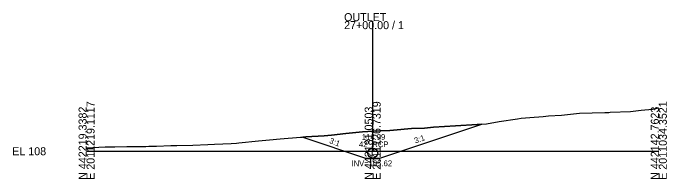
# Model space of a CAD drawing. Extents: x -26 to 1203, y -15 to 9526.
# Drawn here: x 974.3 to 1202.8, y 6990.3 to 7048.4 of the extents above; entities that cross this region are included whole.
import ezdxf

# ---------------------------------------------------------------- set-up
doc = ezdxf.new("R2010")
doc.units = 0
for name, color, linetype in [('Exist Cross Section Cell', 7, 'Continuous'), ('Exist XS Center Line Elevation Label', 7, 'Continuous'), ('Exist XS Ground Line', 7, 'Continuous'), ('Prop XS DDE', 7, 'Continuous'), ('Prop XS DDE Earthwork Shape', 7, 'Continuous'), ('Prop XS DDE Slope Text', 7, 'Continuous'), ('Prop XSC Text', 7, 'Continuous')]:
    doc.layers.add(name, color=color, linetype=linetype)

msp = doc.modelspace()

# ---------------------------------------------------------------- linework, layer by layer
at = {"layer": 'Exist Cross Section Cell'}
for p, q in [((1100, 7000), (1100, 7045.53)), ((1000, 7000), (1100, 7000)), ((1100, 7000), (1200, 7000))]:
    msp.add_line(p, q, dxfattribs=at)
at = {"layer": 'Exist XS Ground Line'}
msp.add_lwpolyline([(1000, 7001.15), (1006.47, 7001.49), (1009.86, 7001.55), (1014.12, 7001.69), (1020.69, 7001.72), (1021.77, 7001.74), (1024.39, 7001.82), (1029.43, 7002), (1031.51, 7001.99), (1037.08, 7002.16), (1042.34, 7002.33), (1044.73, 7002.48), (1050.51, 7002.74), (1052.38, 7002.85), (1053.16, 7002.92), (1060.04, 7003.66), (1063.99, 7004.05), (1067.69, 7004.31), (1074.81, 7004.88), (1075.34, 7004.91), (1076.63, 7004.99), (1083, 7005.37), (1085.64, 7005.63), (1090.65, 7006.27), (1096.46, 7006.74), (1098.3, 7006.91), (1100, 7006.99), (1102.74, 7007.12), (1105.96, 7007.26), (1107.29, 7007.38), (1113.61, 7007.91), (1118.11, 7008.12), (1121.26, 7008.38), (1128.94, 7008.91), (1136.57, 7009.37), (1139.76, 7009.63), (1144.22, 7010.41), (1150.59, 7011.34), (1151.87, 7011.57), (1154.98, 7011.78), (1159.53, 7012.19), (1161.41, 7012.43), (1165.96, 7012.6), (1172.24, 7013.28), (1181.1, 7013.51), (1182.49, 7013.6), (1183.06, 7013.65), (1190.14, 7013.88), (1193.89, 7014.4), (1197.79, 7014.73), (1200, 7015.18)], dxfattribs=at)
at = {"layer": 'Prop XS DDE'}
for p, q in [((1102.5, 6997.62), (1138.13, 7009.5)), ((1075.58, 7004.93), (1097.5, 6997.62)), ((1097.5, 6997.62), (1102.5, 6997.62))]:
    msp.add_line(p, q, dxfattribs=at)
at = {"layer": 'Prop XS DDE Earthwork Shape'}
msp.add_lwpolyline([(1102.5, 6997.62), (1138.13, 7009.5), (1136.57, 7009.37), (1128.94, 7008.91), (1121.26, 7008.38), (1118.11, 7008.12), (1113.61, 7007.91), (1107.29, 7007.38), (1105.96, 7007.26), (1102.74, 7007.12), (1100, 7006.99), (1098.3, 7006.91), (1096.46, 7006.74), (1090.65, 7006.27), (1085.64, 7005.63), (1083, 7005.37), (1076.63, 7004.99), (1075.58, 7004.93), (1097.5, 6997.62)], close=True, dxfattribs=at)
at = {"layer": 'Prop XSC Text'}
msp.add_circle((1100, 6999.37), 1.75, dxfattribs=at)

# ---------------------------------------------------------------- texts
at = {"layer": 'Exist Cross Section Cell'}
for s, p in [('OUTLET', (1090, 7045.53)), ('27+00.00 / 1', (1090, 7042.73)), ('EL 108', (974, 6998.6))]:
    msp.add_text(s, height=2.8, dxfattribs=at).set_placement(p)
for s, p in [('E 2011219.1117', (1002.8, 6990)), ('E 2011126.7319', (1102.8, 6990)), ('E 2011034.3521', (1202.8, 6990)), ('N 442219.3382', (1000, 6990)), ('N 442181.0503', (1100, 6990)), ('N 442142.7623', (1200, 6990))]:
    msp.add_text(s, height=2.8, rotation=90, dxfattribs=at).set_placement(p)
at = {"layer": 'Exist XS Center Line Elevation Label'}
msp.add_text('114.99', height=2, dxfattribs=at).set_placement((1096.21, 7003.99))
at = {"layer": 'Prop XS DDE Slope Text'}
for rotation, p in [(339.0265, (1084.67, 7002.93)), (19.4493, (1114.93, 7002.69))]:
    msp.add_text('3:1', height=2, rotation=rotation, dxfattribs=at).set_placement(p)
at = {"layer": 'Prop XSC Text'}
for s, p in [('42" RCP', (1095.2, 7001.43)), ('INV=105.62', (1092.59, 6994.77))]:
    msp.add_text(s, height=2, dxfattribs=at).set_placement(p)

doc.saveas('drawing.dxf')
